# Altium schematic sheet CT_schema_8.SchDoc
size 147 x 119 mm
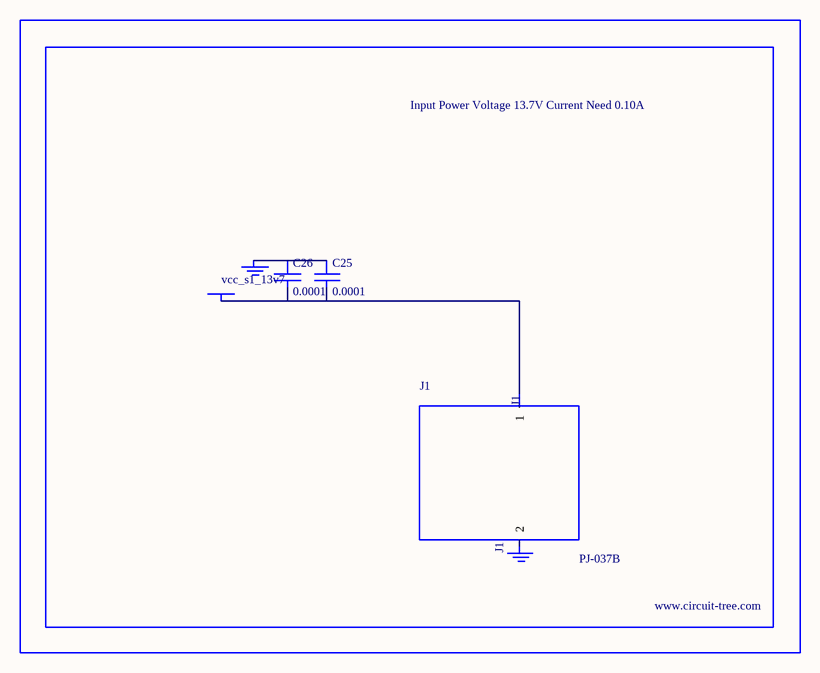
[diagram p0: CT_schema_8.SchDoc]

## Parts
BORDER7  (no value)
C25  0.0001  [EXV-9H]
C26  0.0001  [EXV-9H]
GND_INSTANCE_7_0  (no value)
GND_INSTANCE_7_1  (no value)
J1  PJ-037B  [PJ-037B_PACKAGE]
POWER_INSTANCE_7_0  vcc_s1_13v7

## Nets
NetC25_1: C25.1 C26.1 GND_INSTANCE_7_0.0(GND)
NetC25_2: C25.2 C26.2 J1.1 POWER_INSTANCE_7_0.0(PWR)

Not connected (* = marked no-connect by the designer): GND_INSTANCE_7_1 0(GND); J1 2

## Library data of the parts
BORDER7 = BORDER_PAGE7
C25 C26 = EDK107M035A9HAA
GND_INSTANCE_7_0 GND_INSTANCE_7_1 = GND
POWER_INSTANCE_7_0 = PWR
